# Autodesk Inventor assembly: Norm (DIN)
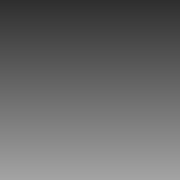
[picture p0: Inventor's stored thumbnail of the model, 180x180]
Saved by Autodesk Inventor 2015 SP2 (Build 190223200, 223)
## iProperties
Shininess: 64.0
Length Units: 11269
Angle Units: 11279
Time Units: 11290
Mass Units: 11283
Length Display Precision: 3
Angle Display Precision: 2
Compacted: True
Created: 2002-07
Part Number: Norm (DIN)
Document SubType Name: Assembly
Density: 0.0
Volumn: 0.0
Area: 0.0
PropertySet Name: Model Information
Control State: 0
Master: False
Checked Out: False
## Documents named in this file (1)
- E:\Tigers SVN\mechanik\2016\Inventor\Templates\Norm.iam
